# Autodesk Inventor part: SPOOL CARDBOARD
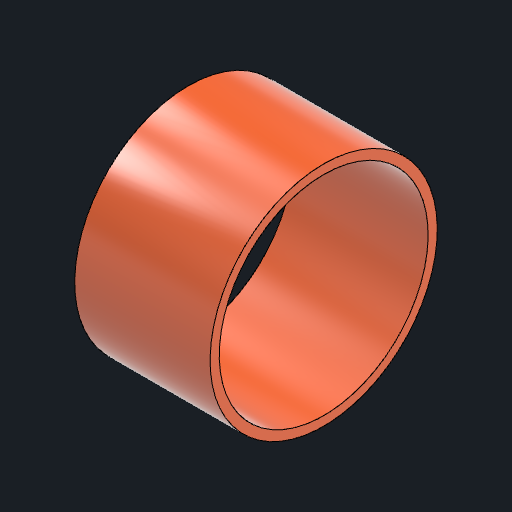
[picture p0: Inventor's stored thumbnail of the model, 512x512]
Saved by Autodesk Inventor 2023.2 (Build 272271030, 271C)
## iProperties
Created: 2022-11
Part Number: SPOOL CARDBOARD
Material: Generic
Document SubType Name: Modeling
Designer: AR
Mass: 70.4345 g
Surface Area: 376.049 cm^2
Volume: 70.4345 cm^3
Density: 1 g/cm^3
Appearance: Smooth - Ash
Author: AR
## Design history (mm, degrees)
derived "_2 SPOOL CORD WRAP MP.ipt"
feature "PRUSA SPOOL CARDBOARD::_2 SPOOL CORD WRAP MP.ipt" dims "d0" = 10
tag "TaggingFeature1"
node "PRUSA SPOOL CARDBOARD"
